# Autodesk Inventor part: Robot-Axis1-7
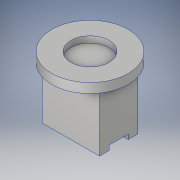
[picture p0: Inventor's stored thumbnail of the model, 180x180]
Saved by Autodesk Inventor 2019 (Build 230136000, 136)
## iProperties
Created: 2018-07
Part Number: Robot-Axis1-7
Material: Aluminum 6061
Description: 123456
Document SubType Name: Modeling
Designer: Power User
Mass: 162915 g
Surface Area: 10619 cm^2
Volume: 18450.2 cm^3
Density: 2.7 g/cm^3
Appearance: Aluminum - Flat
Title: GEAR
Author: Power User
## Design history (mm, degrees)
sketch "Sketch6"
  geometry: L1 (60, 20)-(0, 20); L2 (0, -20)-(60, -20); L3 (60, -20)-(60, 20); L4 (0, 10)-(5, 10); L5 (5, 10)-(5, -10); L6 (5, -10)-(0, -10); L7 (0, 20)-(0, 10); L8 (0, -10)-(0, -20); 4 further points
  constraints: 16 end point, 7 perpendicular, 3 parallel, 2 coincident, 2 horizontal alignment, 2 midpoint, 2 vertical alignment, 1 horizontal
  dimensions: "d44" = 40 distance between parallel lines of L2 L1; "d45" = 20 distance of L4.end L5.end; "d46" = 5 distance from line of L5 point (0, 0); "d47" = 60 distance from line of point (0, 0) L3
extrude "Extrusion5" new body sketch "Sketch6" stored distance "d48" = 60; taper "d49" = 0 deg
sketch "Sketch7"
  geometry: C1 r 40 at (30, 20); 1 further point
  constraints: 1 centre point, 1 coincident
  dimensions: "d50" = 80 diameter of C1
extrude "Extrusion6" join sketch "Sketch7" distance "d51" = 10; taper "d52" = 0 deg
sketch "Sketch8"
  geometry: C1 r 40 at (0, 0) reference; 2 further points
  constraints: 1 coincident
hole "Hole2" sketch "Sketch8" at (0, 0) diameter "d53" = 40; stored, may be unused: countersink angle "d57" = 90 deg, drill point angle "d59" = 0 deg; dims "d54" = 6, "d55" = 4, "d56" = 2, "d58" = 6.5
body "Solid2"
